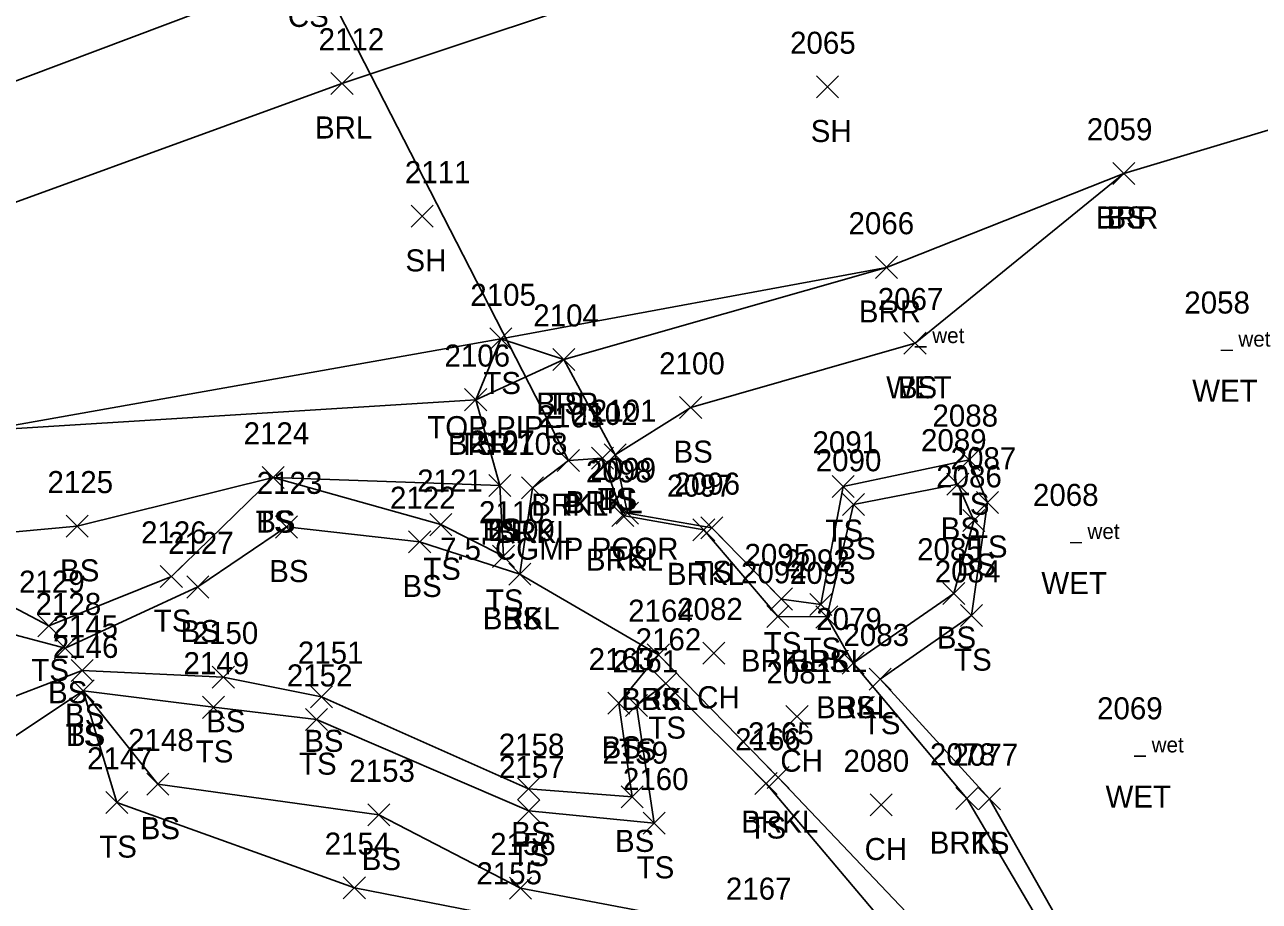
# Model space of a CAD drawing. Extents: x 1502194 to 1507887, y 142265 to 144150.
# Drawn here: x 1506728.1 to 1506840, y 143391.2 to 143470.6 of the extents above; entities that cross this region are included whole.
import ezdxf

# ---------------------------------------------------------------- set-up
doc = ezdxf.new("R2010")
doc.units = 0
for name, color, linetype in [('D_A', 7, 'Continuous'), ('D_C', 7, 'Continuous'), ('D_I', 7, 'Continuous'), ('D_TIC', 7, 'Continuous'), ('DCP', 7, 'Continuous'), ('L_A', 7, 'Continuous'), ('L_C', 7, 'Continuous'), ('L_I', 7, 'Continuous'), ('L_TIC', 7, 'Continuous'), ('LABL', 7, 'Continuous'), ('LAWE', 7, 'Continuous'), ('LELB', 7, 'Continuous'), ('LWET', 7, 'Continuous')]:
    doc.layers.add(name, color=color, linetype=linetype)

msp = doc.modelspace()

# ---------------------------------------------------------------- linework, layer by layer
at = {"layer": 'D_TIC'}
for points in [[(1506776.4, 143430.12), (1506778.4, 143432.12)], [(1506778.4, 143430.12), (1506776.4, 143432.12)]]:
    msp.add_lwpolyline(points, dxfattribs=at)
at = {"layer": 'DCP'}
msp.add_lwpolyline([(1506777.4, 143431.12), (1506698.03, 143585.85)], dxfattribs=at)
at = {"layer": 'L_TIC'}
for points in [[(1506755.88, 143464.31), (1506757.88, 143466.31)], [(1506757.88, 143464.31), (1506755.88, 143466.31)], [(1506799.89, 143463.99), (1506801.89, 143465.99)], [(1506801.89, 143463.99), (1506799.89, 143465.99)], [(1506826.75, 143456.15), (1506828.75, 143458.15)], [(1506828.75, 143456.15), (1506826.75, 143458.15)], [(1506826.75, 143456.15), (1506828.75, 143458.15)], [(1506828.75, 143456.15), (1506826.75, 143458.15)], [(1506763.14, 143452.26), (1506765.14, 143454.26)], [(1506765.14, 143452.26), (1506763.14, 143454.26)], [(1506805.24, 143447.63), (1506807.24, 143449.63)], [(1506807.24, 143447.63), (1506805.24, 143449.63)], [(1506770.28, 143441.14), (1506772.28, 143443.14)], [(1506772.28, 143441.14), (1506770.28, 143443.14)], [(1506807.83, 143440.76), (1506809.83, 143442.76)], [(1506809.83, 143440.76), (1506807.83, 143442.76)], [(1506775.99, 143439.27), (1506777.99, 143441.27)], [(1506777.99, 143439.27), (1506775.99, 143441.27)], [(1506775.99, 143439.27), (1506777.99, 143441.27)], [(1506777.99, 143439.27), (1506775.99, 143441.27)], [(1506768, 143435.63), (1506770, 143437.63)], [(1506770, 143435.63), (1506768, 143437.63)], [(1506768, 143435.63), (1506770, 143437.63)], [(1506770, 143435.63), (1506768, 143437.63)], [(1506787.49, 143434.92), (1506789.49, 143436.92)], [(1506789.49, 143434.92), (1506787.49, 143436.92)], [(1506776.4, 143430.12), (1506778.4, 143432.12)], [(1506778.4, 143430.12), (1506776.4, 143432.12)], [(1506779.5, 143430.34), (1506781.5, 143432.34)], [(1506781.5, 143430.34), (1506779.5, 143432.34)], [(1506780.64, 143430.63), (1506782.64, 143432.63)], [(1506782.64, 143430.63), (1506780.64, 143432.63)], [(1506780.64, 143430.63), (1506782.64, 143432.63)], [(1506782.64, 143430.63), (1506780.64, 143432.63)], [(1506812.75, 143430.19), (1506814.75, 143432.19)], [(1506814.75, 143430.19), (1506812.75, 143432.19)], [(1506749.65, 143428.58), (1506751.65, 143430.58)], [(1506751.65, 143428.58), (1506749.65, 143430.58)], [(1506749.65, 143428.58), (1506751.65, 143430.58)], [(1506751.65, 143428.58), (1506749.65, 143430.58)], [(1506770.18, 143427.84), (1506772.18, 143429.84)], [(1506772.18, 143427.84), (1506770.18, 143429.84)], [(1506770.18, 143427.84), (1506772.18, 143429.84)], [(1506772.18, 143427.84), (1506770.18, 143429.84)], [(1506773.14, 143427.63), (1506775.14, 143429.63)], [(1506775.14, 143427.63), (1506773.14, 143429.63)], [(1506801.31, 143427.76), (1506803.31, 143429.76)], [(1506803.31, 143427.76), (1506801.31, 143429.76)], [(1506811.72, 143427.96), (1506813.72, 143429.96)], [(1506813.72, 143427.96), (1506811.72, 143429.96)], [(1506814.4, 143426.32), (1506816.4, 143428.32)], [(1506816.4, 143426.32), (1506814.4, 143428.32)], [(1506781.34, 143425.13), (1506783.34, 143427.13)], [(1506783.34, 143425.13), (1506781.34, 143427.13)], [(1506781.75, 143425.35), (1506783.75, 143427.35)], [(1506783.75, 143425.35), (1506781.75, 143427.35)], [(1506802.26, 143426.14), (1506804.26, 143428.14)], [(1506804.26, 143426.14), (1506802.26, 143428.14)], [(1506731.88, 143424.16), (1506733.88, 143426.16)], [(1506733.88, 143424.16), (1506731.88, 143426.16)], [(1506750.84, 143424.09), (1506752.84, 143426.09)], [(1506752.84, 143424.09), (1506750.84, 143426.09)], [(1506764.83, 143424.3), (1506766.83, 143426.3)], [(1506766.83, 143424.3), (1506764.83, 143426.3)], [(1506789.41, 143424.02), (1506791.41, 143426.02)], [(1506791.41, 143424.02), (1506789.41, 143426.02)], [(1506813.15, 143424.68), (1506815.15, 143426.68)], [(1506815.15, 143424.68), (1506813.15, 143426.68)], [(1506788.68, 143423.84), (1506790.68, 143425.84)], [(1506790.68, 143423.84), (1506788.68, 143425.84)], [(1506762.92, 143422.74), (1506764.92, 143424.74)], [(1506764.92, 143422.74), (1506762.92, 143424.74)], [(1506770.51, 143421.43), (1506772.51, 143423.43)], [(1506772.51, 143421.43), (1506770.51, 143423.43)], [(1506740.41, 143419.6), (1506742.41, 143421.6)], [(1506742.41, 143419.6), (1506740.41, 143421.6)], [(1506772, 143419.81), (1506774, 143421.81)], [(1506774, 143419.81), (1506772, 143421.81)], [(1506772, 143419.81), (1506774, 143421.81)], [(1506774, 143419.81), (1506772, 143421.81)], [(1506742.8, 143418.65), (1506744.8, 143420.65)], [(1506744.8, 143418.65), (1506742.8, 143420.65)], [(1506795.71, 143417.56), (1506797.71, 143419.56)], [(1506797.71, 143417.56), (1506795.71, 143419.56)], [(1506811.36, 143418.07), (1506813.36, 143420.07)], [(1506813.36, 143418.07), (1506811.36, 143420.07)], [(1506799.3, 143417.06), (1506801.3, 143419.06)], [(1506801.3, 143417.06), (1506799.3, 143419.06)], [(1506729.3, 143415.13), (1506731.3, 143417.13)], [(1506731.3, 143415.13), (1506729.3, 143417.13)], [(1506795.38, 143415.98), (1506797.38, 143417.98)], [(1506797.38, 143415.98), (1506795.38, 143417.98)], [(1506799.83, 143415.93), (1506801.83, 143417.93)], [(1506801.83, 143415.93), (1506799.83, 143417.93)], [(1506799.83, 143415.93), (1506801.83, 143417.93)], [(1506801.83, 143415.93), (1506799.83, 143417.93)], [(1506812.96, 143416.06), (1506814.96, 143418.06)], [(1506814.96, 143416.06), (1506812.96, 143418.06)], [(1506730.79, 143413.11), (1506732.79, 143415.11)], [(1506732.79, 143413.11), (1506730.79, 143415.11)], [(1506784.56, 143412.5), (1506786.56, 143414.5)], [(1506786.56, 143412.5), (1506784.56, 143414.5)], [(1506784.56, 143412.5), (1506786.56, 143414.5)], [(1506786.56, 143412.5), (1506784.56, 143414.5)], [(1506789.59, 143412.65), (1506791.59, 143414.65)], [(1506791.59, 143412.65), (1506789.59, 143414.65)], [(1506802.22, 143411.75), (1506804.22, 143413.75)], [(1506804.22, 143411.75), (1506802.22, 143413.75)], [(1506802.22, 143411.75), (1506804.22, 143413.75)], [(1506804.22, 143411.75), (1506802.22, 143413.75)], [(1506732.32, 143411.08), (1506734.32, 143413.08)], [(1506734.32, 143411.08), (1506732.32, 143413.08)], [(1506745.12, 143410.48), (1506747.12, 143412.48)], [(1506747.12, 143410.48), (1506745.12, 143412.48)], [(1506785.24, 143409.9), (1506787.24, 143411.9)], [(1506787.24, 143409.9), (1506785.24, 143411.9)], [(1506804.68, 143410.3), (1506806.68, 143412.3)], [(1506806.68, 143410.3), (1506804.68, 143412.3)], [(1506732.41, 143409.22), (1506734.41, 143411.22)], [(1506734.41, 143409.22), (1506732.41, 143411.22)], [(1506732.41, 143409.22), (1506734.41, 143411.22)], [(1506734.41, 143409.22), (1506732.41, 143411.22)], [(1506732.41, 143409.22), (1506734.41, 143411.22)], [(1506734.41, 143409.22), (1506732.41, 143411.22)], [(1506754.01, 143408.7), (1506756.01, 143410.7)], [(1506756.01, 143408.7), (1506754.01, 143410.7)], [(1506744.22, 143407.74), (1506746.22, 143409.74)], [(1506746.22, 143407.74), (1506744.22, 143409.74)], [(1506780.98, 143408.11), (1506782.98, 143410.11)], [(1506782.98, 143408.11), (1506780.98, 143410.11)], [(1506782.59, 143407.91), (1506784.59, 143409.91)], [(1506784.59, 143407.91), (1506782.59, 143409.91)], [(1506753.57, 143406.63), (1506755.57, 143408.63)], [(1506755.57, 143406.63), (1506753.57, 143408.63)], [(1506797.13, 143406.9), (1506799.13, 143408.9)], [(1506799.13, 143406.9), (1506797.13, 143408.9)], [(1506739.19, 143400.78), (1506741.19, 143402.78)], [(1506741.19, 143400.78), (1506739.19, 143402.78)], [(1506794.32, 143400.84), (1506796.32, 143402.84)], [(1506796.32, 143400.84), (1506794.32, 143402.84)], [(1506795.43, 143401.38), (1506797.43, 143403.38)], [(1506797.43, 143401.38), (1506795.43, 143403.38)], [(1506772.79, 143400.35), (1506774.79, 143402.35)], [(1506774.79, 143400.35), (1506772.79, 143402.35)], [(1506782.19, 143399.63), (1506784.19, 143401.63)], [(1506784.19, 143399.63), (1506782.19, 143401.63)], [(1506812.52, 143399.48), (1506814.52, 143401.48)], [(1506814.52, 143399.48), (1506812.52, 143401.48)], [(1506814.57, 143399.44), (1506816.57, 143401.44)], [(1506816.57, 143399.44), (1506814.57, 143401.44)], [(1506735.47, 143399.11), (1506737.47, 143401.11)], [(1506737.47, 143399.11), (1506735.47, 143401.11)], [(1506772.81, 143398.34), (1506774.81, 143400.34)], [(1506774.81, 143398.34), (1506772.81, 143400.34)], [(1506804.77, 143398.89), (1506806.77, 143400.89)], [(1506806.77, 143398.89), (1506804.77, 143400.89)], [(1506759.23, 143397.98), (1506761.23, 143399.98)], [(1506761.23, 143397.98), (1506759.23, 143399.98)], [(1506784.18, 143397.23), (1506786.18, 143399.23)], [(1506786.18, 143397.23), (1506784.18, 143399.23)], [(1506757, 143391.38), (1506759, 143393.38)], [(1506759, 143391.38), (1506757, 143393.38)], [(1506772.06, 143391.35), (1506774.06, 143393.35)], [(1506774.06, 143391.35), (1506772.06, 143393.35)]]:
    msp.add_lwpolyline(points, dxfattribs=at)
at = {"layer": 'LABL'}
for points in [[(1506925.15, 143533.52), (1506885.27, 143516.72), (1506839.01, 143491.82), (1506812.47, 143480.11), (1506797.79, 143478.92), (1506756.88, 143465.31), (1506714.98, 143450.06), (1506660.24, 143438.77), (1506613.3, 143423.94), (1506616.52, 143414.64)], [(1506850.82, 143464.05), (1506827.75, 143457.15), (1506806.24, 143448.63), (1506776.99, 143440.27), (1506769, 143436.63), (1506724.43, 143433.85), (1506664.3, 143424.7), (1506616.52, 143414.64)]]:
    msp.add_lwpolyline(points, dxfattribs=at)
at = {"layer": 'LAWE'}
msp.add_lwpolyline([(1506829.7, 143367.6), (1506826.12, 143374.97), (1506823.75, 143383.11), (1506813.52, 143400.48), (1506803.22, 143412.75), (1506800.83, 143416.93), (1506796.38, 143416.98), (1506789.68, 143424.84), (1506782.34, 143426.13), (1506780.5, 143431.34), (1506777.4, 143431.12), (1506774.14, 143428.63), (1506773, 143420.81), (1506785.56, 143413.5), (1506796.43, 143402.38), (1506812.68, 143385.26), (1506814.85, 143376.4), (1506822.31, 143364.53)], dxfattribs=at)
at = {"layer": 'LELB'}
for points in [[(1506885.27, 143516.72), (1506836.36, 143503.21), (1506808.72, 143492.99), (1506794.07, 143487.49), (1506753.53, 143475.43), (1506709.32, 143458.78), (1506657.01, 143447.54), (1506608.42, 143435.74), (1506565.83, 143422.65), (1506556.41, 143414.68), (1506554.63, 143405.1), (1506570.25, 143400.38), (1506594.37, 143381.91)], [(1506827.75, 143457.15), (1506808.83, 143441.76), (1506788.49, 143435.92), (1506781.64, 143431.63)], [(1506771.28, 143442.14), (1506806.24, 143448.63)], [(1506831, 143368.57), (1506828.29, 143375.32), (1506824.82, 143384.1), (1506815.57, 143400.44), (1506805.68, 143411.3), (1506813.96, 143417.06), (1506815.4, 143427.32), (1506813.75, 143431.19), (1506802.31, 143428.76), (1506800.3, 143418.06), (1506796.71, 143418.56), (1506790.41, 143425.02), (1506782.75, 143426.35), (1506781.64, 143431.63), (1506776.99, 143440.27), (1506771.28, 143442.14), (1506769, 143436.63), (1506771.18, 143428.84), (1506771.51, 143422.43), (1506765.83, 143425.3), (1506750.65, 143429.58), (1506741.41, 143420.6), (1506730.3, 143416.13), (1506716.06, 143423.61)], [(1506771.28, 143442.14), (1506724.43, 143433.85)], [(1506771.18, 143428.84), (1506750.65, 143429.58), (1506732.88, 143425.16), (1506716.06, 143423.61)], [(1506803.22, 143412.75), (1506812.36, 143419.07), (1506814.15, 143425.68), (1506812.72, 143428.96), (1506803.26, 143427.14), (1506800.83, 143416.93)], [(1506773, 143420.81), (1506763.92, 143423.74), (1506751.84, 143425.09), (1506743.8, 143419.65), (1506731.79, 143414.11), (1506717.05, 143418.01), (1506689.37, 143414.59), (1506679.26, 143405.25), (1506682.71, 143395.11), (1506700.01, 143398.02), (1506719.4, 143395.12), (1506721.34, 143407.47), (1506733.32, 143412.08), (1506746.12, 143411.48), (1506755.01, 143409.7), (1506773.79, 143401.35), (1506783.19, 143400.63), (1506781.98, 143409.11), (1506785.56, 143413.5)], [(1506680.81, 143385.8), (1506700.49, 143392.33), (1506721.56, 143393.15), (1506724.7, 143404.46), (1506733.41, 143410.22), (1506745.22, 143408.74), (1506754.57, 143407.63), (1506773.81, 143399.34), (1506785.18, 143398.23), (1506783.59, 143408.91), (1506786.24, 143410.9), (1506795.32, 143401.84), (1506810.64, 143383.72), (1506813.18, 143377.58), (1506821.73, 143363.41)], [(1506733.41, 143410.22), (1506740.19, 143401.78), (1506760.23, 143398.98), (1506773.06, 143392.35), (1506794.42, 143388.3), (1506810.64, 143383.72)], [(1506733.41, 143410.22), (1506736.47, 143400.11), (1506758, 143392.38), (1506771.75, 143389.69), (1506794.74, 143386.01), (1506813.18, 143377.58)]]:
    msp.add_lwpolyline(points, dxfattribs=at)

# ---------------------------------------------------------------- texts
at = {"layer": 'D_A'}
msp.add_text('P', height=2, dxfattribs=at).set_placement((1506776.78, 143426.12))
at = {"layer": 'D_C'}
msp.add_text("7.5' CGMP POOR", height=2, dxfattribs=at).set_placement((1506765.77, 143422.12))
at = {"layer": 'D_I'}
msp.add_text('2103', height=2, dxfattribs=at).set_placement((1506774.63, 143434.12))
at = {"layer": 'L_A'}
for s, p in [('CS', (1506751.97, 143470.43)), ('BRL', (1506754.43, 143460.31)), ('SH', (1506799.37, 143459.99)), ('BRR', (1506825.23, 143452.15)), ('BS', (1506826.19, 143452.15)), ('SH', (1506762.63, 143448.26)), ('BRR', (1506803.73, 143443.63)), ('TS', (1506769.69, 143437.14)), ('WET', (1506806.21, 143436.76)), ('BS', (1506807.27, 143436.76)), ('WET', (1506833.96, 143436.44)), ('BRR', (1506774.48, 143435.27)), ('TS', (1506775.4, 143435.27)), ('BRR', (1506766.48, 143431.63)), ('TS', (1506767.4, 143431.63)), ('BS', (1506786.93, 143430.92)), ('BRKL', (1506777.14, 143426.34)), ('TS', (1506780.05, 143426.63)), ('BS', (1506780.08, 143426.63)), ('TS', (1506812.16, 143426.19)), ('BRKL', (1506774.04, 143426.12)), ('TS', (1506749.06, 143424.58)), ('BS', (1506749.1, 143424.58)), ('BS', (1506811.16, 143423.96)), ('TS', (1506769.59, 143423.84)), ('BS', (1506769.62, 143423.84)), ('BRKL', (1506770.79, 143423.63)), ('TS', (1506800.71, 143423.76)), ('BS', (1506801.7, 143422.14)), ('TS', (1506813.8, 143422.32)), ('BRKL', (1506778.99, 143421.13)), ('TS', (1506781.16, 143421.35)), ('BS', (1506812.59, 143420.68)), ('BS', (1506731.32, 143420.16)), ('BS', (1506750.28, 143420.09)), ('TS', (1506764.24, 143420.3)), ('BRKL', (1506786.33, 143419.84)), ('TS', (1506788.82, 143420.02)), ('BS', (1506762.36, 143418.74)), ('WET', (1506820.28, 143419)), ('TS', (1506769.92, 143417.43)), ('TS', (1506739.82, 143415.6)), ('BRKL', (1506769.64, 143415.81)), ('BS', (1506771.44, 143415.81)), ('BS', (1506742.24, 143414.65)), ('BS', (1506810.8, 143414.07)), ('TS', (1506795.12, 143413.56)), ('TS', (1506798.71, 143413.06)), ('BRKL', (1506793.03, 143411.98)), ('BRKL', (1506797.48, 143411.93)), ('BS', (1506799.27, 143411.93)), ('TS', (1506812.37, 143412.06)), ('TS', (1506728.71, 143411.13)), ('BS', (1506730.23, 143409.11)), ('BRKL', (1506782.21, 143408.5)), ('BS', (1506784.01, 143408.5)), ('CH', (1506789.08, 143408.65)), ('BRKL', (1506799.86, 143407.75)), ('BS', (1506801.66, 143407.75)), ('BS', (1506731.77, 143407.08)), ('BS', (1506744.56, 143406.48)), ('TS', (1506804.09, 143406.3)), ('TS', (1506731.82, 143405.22)), ('TS', (1506731.82, 143405.22)), ('BS', (1506731.85, 143405.22)), ('TS', (1506784.65, 143405.9)), ('BS', (1506753.45, 143404.7)), ('BS', (1506780.42, 143404.11)), ('TS', (1506781.99, 143403.91)), ('TS', (1506743.62, 143403.74)), ('CH', (1506796.62, 143402.9)), ('TS', (1506752.98, 143402.63)), ('WET', (1506826.1, 143399.65)), ('BRKL', (1506793.07, 143397.38)), ('BS', (1506738.63, 143396.78)), ('BS', (1506772.23, 143396.35)), ('TS', (1506793.73, 143396.84)), ('TS', (1506734.87, 143395.11)), ('BS', (1506781.63, 143395.63)), ('CH', (1506804.26, 143394.89)), ('BRKL', (1506810.16, 143395.48)), ('TS', (1506813.98, 143395.44)), ('BS', (1506758.67, 143393.98)), ('TS', (1506772.22, 143394.34)), ('TS', (1506783.59, 143393.23))]:
    msp.add_text(s, height=2, dxfattribs=at).set_placement(p)
at = {"layer": 'L_C'}
msp.add_text('TOP PIPE', height=2, dxfattribs=at).set_placement((1506764.61, 143433.14))
at = {"layer": 'L_I'}
for s, p in [('2112', (1506754.76, 143468.31)), ('2065', (1506797.5, 143467.99)), ('2059', (1506824.4, 143460.15)), ('2059', (1506824.4, 143460.15)), ('2111', (1506762.58, 143456.26)), ('2066', (1506802.8, 143451.63)), ('2105', (1506768.51, 143445.14)), ('2067', (1506805.45, 143444.76)), ('2067', (1506805.45, 143444.76)), ('2058', (1506833.24, 143444.44)), ('2104', (1506774.22, 143443.27)), ('2104', (1506774.22, 143443.27)), ('2106', (1506766.17, 143439.63)), ('2106', (1506766.17, 143439.63)), ('2100', (1506785.63, 143438.92)), ('2103', (1506774.63, 143434.12)), ('2102', (1506777.72, 143434.34)), ('2101', (1506779.44, 143434.63)), ('2101', (1506779.44, 143434.63)), ('2088', (1506810.41, 143434.19)), ('2124', (1506747.96, 143432.58)), ('2124', (1506747.96, 143432.58)), ('2107', (1506768.41, 143431.84)), ('2107', (1506768.41, 143431.84)), ('2091', (1506799.53, 143431.76)), ('2089', (1506809.37, 143431.96)), ('2108', (1506771.37, 143431.63)), ('2090', (1506799.83, 143430.14)), ('2087', (1506812.06, 143430.32)), ('2098', (1506779, 143429.13)), ('2099', (1506779.4, 143429.35)), ('2086', (1506810.75, 143428.68)), ('2125', (1506730.18, 143428.16)), ('2123', (1506749.15, 143428.09)), ('2121', (1506763.7, 143428.3)), ('2097', (1506786.34, 143427.84)), ('2096', (1506787.02, 143428.02)), ('2122', (1506761.23, 143426.74)), ('2068', (1506819.52, 143427)), ('2110', (1506769.3, 143425.43)), ('2126', (1506738.66, 143423.6)), ('2109', (1506770.22, 143423.81)), ('2109', (1506770.22, 143423.81)), ('2127', (1506741.11, 143422.65)), ('2085', (1506809.02, 143422.07)), ('2095', (1506793.37, 143421.56)), ('2092', (1506796.96, 143421.06)), ('2094', (1506793.05, 143419.98)), ('2093', (1506797.49, 143419.93)), ('2093', (1506797.49, 143419.93)), ('2084', (1506810.62, 143420.06)), ('2129', (1506727.6, 143419.13)), ('2128', (1506729.1, 143417.11)), ('2164', (1506782.82, 143416.5)), ('2164', (1506782.82, 143416.5)), ('2082', (1506787.26, 143416.65)), ('2145', (1506730.63, 143415.08)), ('2079', (1506799.87, 143415.75)), ('2079', (1506799.87, 143415.75)), ('2150', (1506743.34, 143414.48)), ('2162', (1506783.5, 143413.9)), ('2083', (1506802.34, 143414.3)), ('2146', (1506730.66, 143413.22)), ('2146', (1506730.66, 143413.22)), ('2146', (1506730.66, 143413.22)), ('2149', (1506742.51, 143411.74)), ('2151', (1506752.88, 143412.7)), ('2163', (1506779.24, 143412.11)), ('2161', (1506781.41, 143411.91)), ('2152', (1506751.88, 143410.63)), ('2081', (1506795.36, 143410.9)), ('2069', (1506825.33, 143407.65)), ('2165', (1506793.69, 143405.38)), ('2148', (1506737.49, 143404.78)), ('2158', (1506771.09, 143404.35)), ('2166', (1506792.52, 143404.84)), ('2147', (1506733.77, 143403.11)), ('2159', (1506780.49, 143403.63)), ('2080', (1506802.35, 143402.89)), ('2078', (1506810.18, 143403.48)), ('2077', (1506812.23, 143403.44)), ('2153', (1506757.54, 143401.98)), ('2157', (1506771.11, 143402.34)), ('2160', (1506782.35, 143401.23)), ('2154', (1506755.31, 143395.38)), ('2156', (1506770.31, 143395.35)), ('2155', (1506769.06, 143392.69)), ('2167', (1506791.68, 143391.3))]:
    msp.add_text(s, height=2, dxfattribs=at).set_placement(p)
at = {"layer": 'LWET'}
for p in [(1506808.83, 143441.76), (1506836.58, 143441.44), (1506822.9, 143424), (1506828.72, 143404.65)]:
    msp.add_text('_ wet', height=1.4, dxfattribs=at).set_placement(p)

doc.saveas('drawing.dxf')
